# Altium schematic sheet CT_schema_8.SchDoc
size 278 x 170 mm
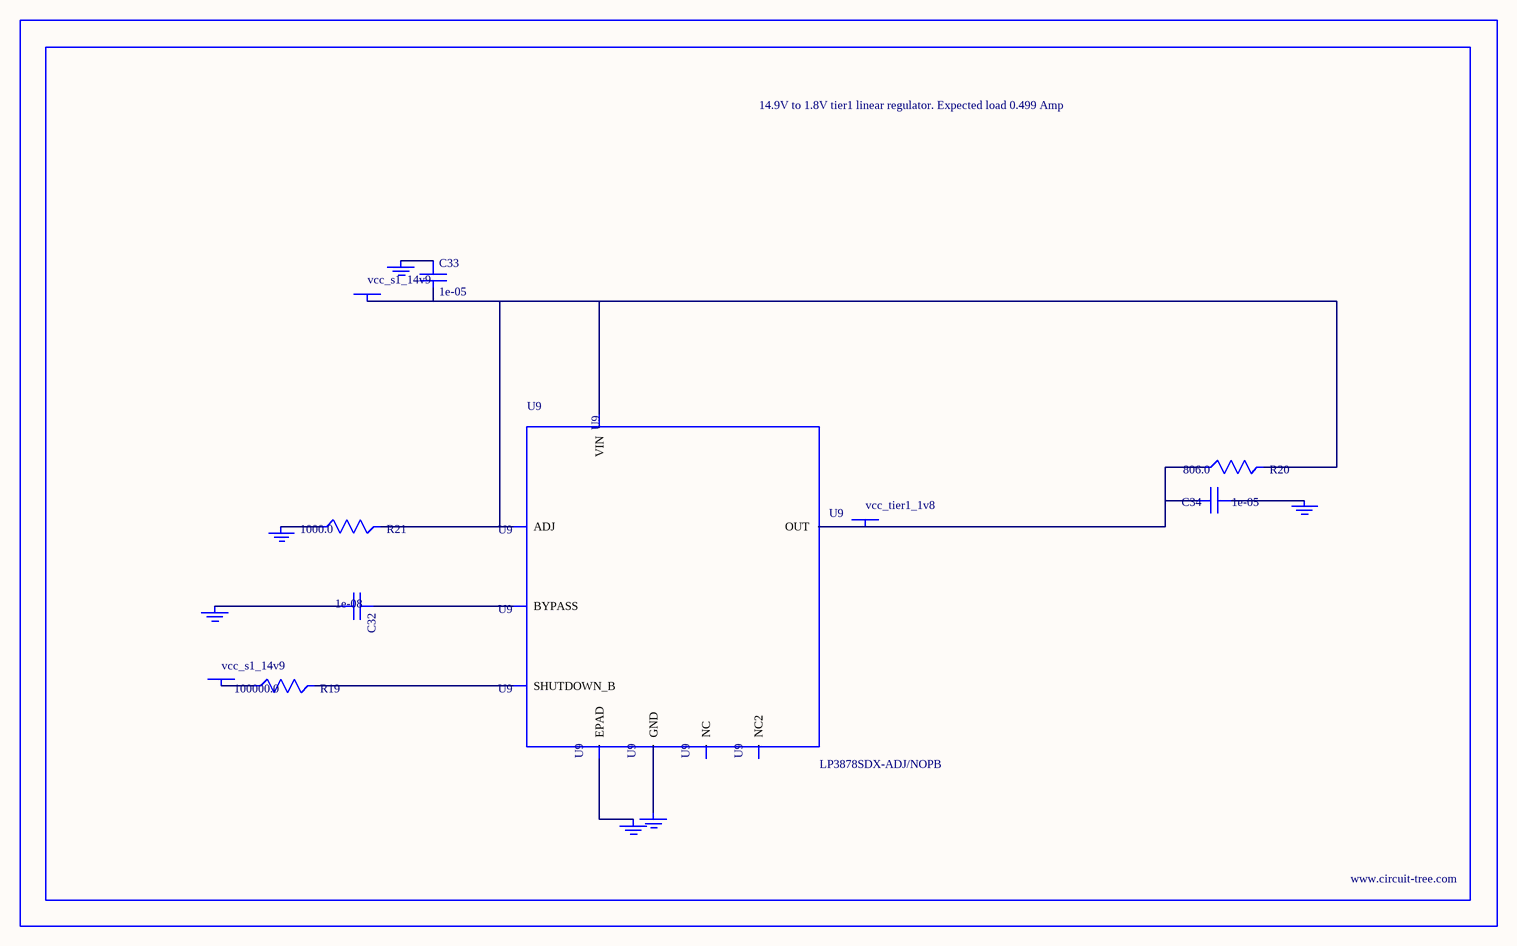
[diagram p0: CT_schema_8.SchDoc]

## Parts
BORDER7  (no value)
C32  1e-08  [C0402]
C33  1e-05  [C1210]
C34  1e-05  [C0805]
GND_INSTANCE_7_0  (no value)
GND_INSTANCE_7_1  (no value)
GND_INSTANCE_7_2  (no value)
GND_INSTANCE_7_3  (no value)
GND_INSTANCE_7_4  (no value)
GND_INSTANCE_7_5  (no value)
POWER_INSTANCE_7_0  vcc_s1_14v9
POWER_INSTANCE_7_1  vcc_s1_14v9
POWER_INSTANCE_7_2  vcc_tier1_1v8
R19  100000.0  [R0603]
R20  806.0  [R0603]
R21  1000.0  [R0603]
U9  LP3878SDX-ADJ/NOPB  [WSON-8]

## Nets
NetC32_1: C32.1 U9.1(BYPASS)
NetC32_2: C32.2 GND_INSTANCE_7_0.0(GND)
NetC33_1: C33.1 GND_INSTANCE_7_1.0(GND)
NetC33_2: C33.2 POWER_INSTANCE_7_0.0(PWR) R20.2 R21.2 U9.4(VIN) U9.6(ADJ)
NetC34_1: C34.1 GND_INSTANCE_7_2.0(GND)
NetC34_2: C34.2 POWER_INSTANCE_7_2.0(PWR) R20.1 U9.5(OUT)
NetGND_INSTANCE_7_3_0: GND_INSTANCE_7_3.0(GND) R21.1
NetGND_INSTANCE_7_4_0: GND_INSTANCE_7_4.0(GND) U9.PAD(EPAD)
NetGND_INSTANCE_7_5_0: GND_INSTANCE_7_5.0(GND) U9.3(GND)
NetPOWER_INSTANCE_7_1_0: POWER_INSTANCE_7_1.0(PWR) R19.1
NetR19_2: R19.2 U9.8(SHUTDOWN_B)

Not connected (* = marked no-connect by the designer): U9 2(NC) 7(NC2)

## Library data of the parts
BORDER7 = BORDER_PAGE7
C32 = C0402C103K3RAC
C33 = C1210C106K5PACTU
C34 = GRM219R60J106ME19D
GND_INSTANCE_7_0-GND_INSTANCE_7_5 = GND
POWER_INSTANCE_7_0-POWER_INSTANCE_7_2 = PWR
R19 = RC0603JR-07100KL
R20 = ERJ-3EKF8060V
R21 = RC0603JR-071KL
